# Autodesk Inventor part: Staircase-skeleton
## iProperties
Created: 2006-03
Part Number: Staircase-skeleton
Document SubType Name: Modeling
Designer: Carlo
Author: Carlo
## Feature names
1. Extrusion2
